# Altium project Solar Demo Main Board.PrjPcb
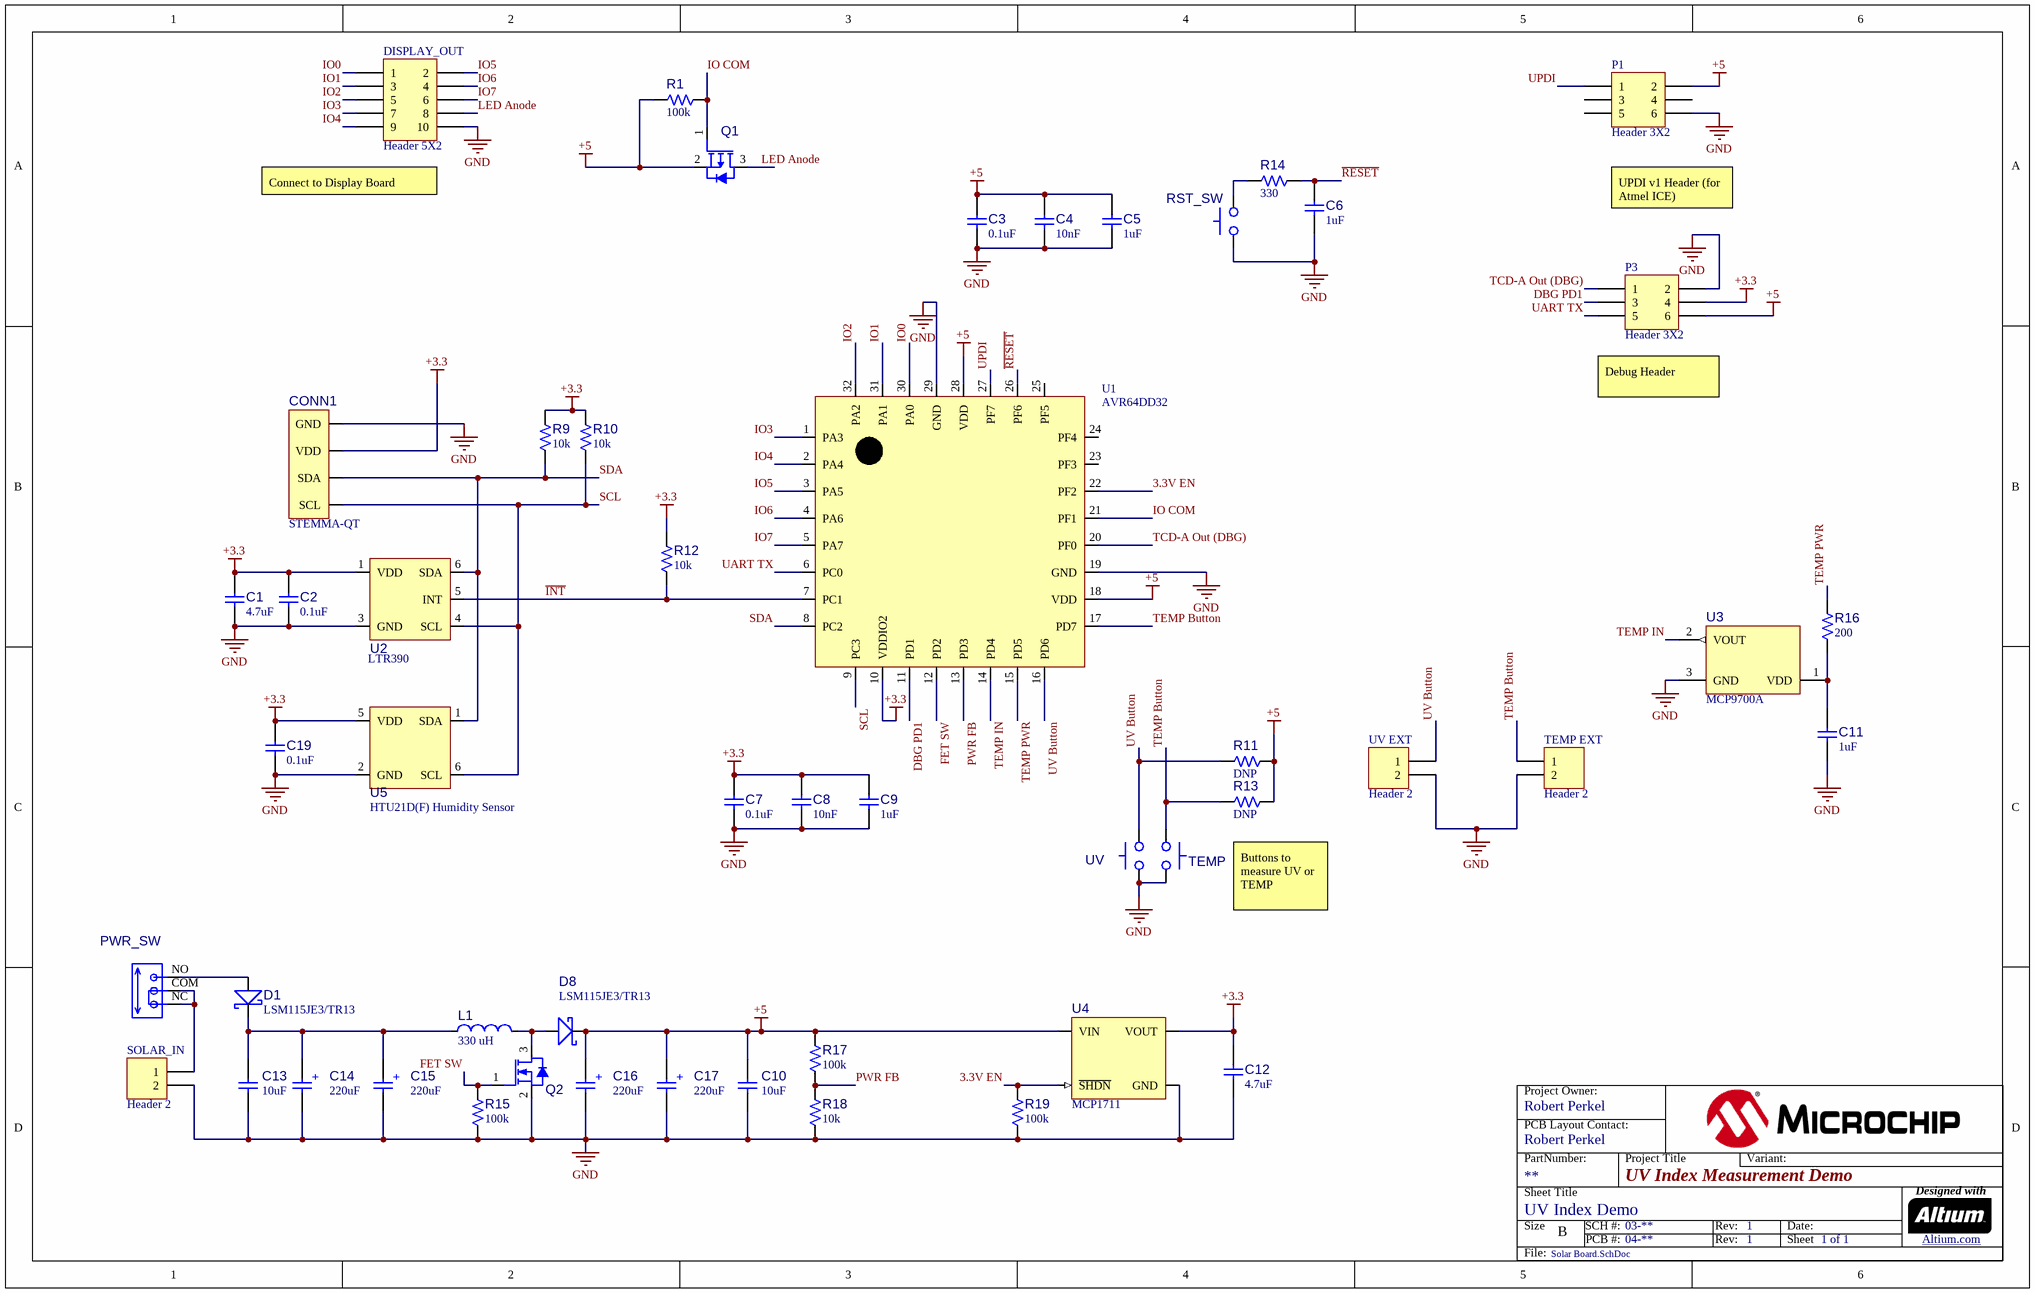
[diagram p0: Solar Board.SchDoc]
ProjectDrawnBy: Robert Perkel; ProjectEngineer: Robert Perkel; ProjectPartNumber: **; ProjectPCBAssyNumber: **; ProjectPCBNumber: **; ProjectRevisionART: 1; ProjectRevisionASSY: **; ProjectRevisionFAB: **; ProjectRevisionSCH: 1; ProjectTitle: UV Index Measurement Demo
1 sheet, 51 parts. Net scope: global (net labels, ports and power ports of the same name join across sheets).
Board file: Solar Board.PcbDoc

## Sheet Solar Board.SchDoc
size B; CompanyName: Microchip Technology Inc.; Organization: Microchip Technology; Address1: 2355 West Chandler Blvd.; Address2: Chandler, AZ  85224; Address4: USA; SheetNumber: 1; SheetTotal: 1; SheetTitle: UV Index Demo

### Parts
C1  value 4.7uF  [0805]  (hidden comment: Capacitor)
C2  value 0.1uF  [0805]  (hidden comment: Capacitor)
C3  value 0.1uF  [0805]  (hidden comment: Capacitor)
C4  value 10nF  [0805]  (hidden comment: Capacitor)
C5  value 1uF  [0805]  (hidden comment: Capacitor)
C6  value 1uF  [0805]  (hidden comment: Capacitor)
C7  value 0.1uF  [0805]  (hidden comment: Capacitor)
C8  value 10nF  [0805]  (hidden comment: Capacitor)
C9  value 1uF  [0805]  (hidden comment: Capacitor)
C10  value 10uF  [0805]  (hidden comment: Capacitor)
C11  value 1uF  [0805]  (hidden comment: Capacitor)
C12  value 4.7uF  [0805]  (hidden comment: Capacitor)
C13  value 10uF  [0805]  (hidden comment: Capacitor)
C14  value 220uF  [2917]  (hidden comment: Polarized Capacitor)
C15  value 220uF  [2917]  (hidden comment: Polarized Capacitor)
C16  value 220uF  [2917]  (hidden comment: Polarized Capacitor)
C17  value 220uF  [2917]  (hidden comment: Polarized Capacitor)
C19  value 0.1uF  [0805]  (hidden comment: Capacitor)
CONN1  STEMMA-QT  [JST-ST]
D1  Part Number: LSM115JE3/TR13  [DO-215AB]  (hidden comment: Schottky)
D8  Part Number: LSM115JE3/TR13  [DO-215AB]  (hidden comment: Schottky)
DISPLAY_OUT  Header 5X2  [HDR2X5]
L1  value 330 uH  [6mm x 6mm Inductor]  (hidden comment: Inductor)
P1  Header 3X2  [HDR2X3]
P3  Header 3X2  [HDR2X3]
PWR_SW  SPDT Slide  [CST11T2CR (SPST)]  (value not drawn)
Q1  PMOS Transistor  [SOT-23]  (value not drawn)
Q2  NMOS Transistor  [SOT-23]  (value not drawn)
R1  value 100k  [0805]  (hidden comment: Resistor)
R9  value 10k  [0805]  (hidden comment: Resistor)
R10  value 10k  [0805]  (hidden comment: Resistor)
R11  value DNP  [0805]  (hidden comment: Resistor)
R12  value 10k  [0805]  (hidden comment: Resistor)
R13  value DNP  [0805]  (hidden comment: Resistor)
R14  value 330  [0805]  (hidden comment: Resistor)
R15  value 100k  [0805]  (hidden comment: Resistor)
R16  value 200  [0805]  (hidden comment: Resistor)
R17  value 100k  [0805]  (hidden comment: Resistor)
R18  value 10k  [0805]  (hidden comment: Resistor)
R19  value 100k  [0805]  (hidden comment: Resistor)
RST_SW  SPST Switch  [KMR7]  (value not drawn)
SOLAR_IN  Header 2  [HDR1X2]
TEMP  SPST Switch  [KSC4]  (value not drawn)
TEMP_EXT  Header 2  [HDR1X2]
U1  AVR64DD32  [TQFP-32]
U2  LTR390  [Extended QFN-6]
U3  value MCP9700A  [SOT-23-3]  (hidden comment: MCP9700(A)_1(A) TO-92-3_SOT-23-3)
U4  MCP1711  [SOT23-5]
U5  HTU21D(F) Humidity Sensor  [HTU21D(F) Extended Package]
UV  SPST Switch  [KSC4]  (value not drawn)
UV_EXT  Header 2  [HDR1X2]

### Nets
+3.3: C1.1 C2.1 C7.1 C8.1 C9.1 C12.1 C19.1 CONN1.2(VDD) P3.4 R9.2 R10.2 R12.2 U1.10(VDDIO2) U2.1(VDD) U4.5(VOUT) U5.5(VDD)
+5: C3.1 C4.1 C5.1 C10.1 C16.A C17.A D8.K(CATHODE) P1.2 P3.6 Q1.2(S) R1.2 R11.1 R13.1 R17.2 U1.18(VDD) U1.28(VDD) U4.1(VIN)
GND: C1.2 C2.2 C3.2 C4.2 C5.2 C6.2 C7.2 C8.2 C9.2 C10.2 C11.2 C12.2 C13.2 C14.K C15.K C16.K C17.K C19.2 CONN1.1(GND) DISPLAY_OUT.10 P1.6 P3.2 Q2.2(S) R15.1 R18.1 R19.1 RST_SW.1 SOLAR_IN.2 TEMP.1 TEMP_EXT.2 U1.19(GND) U1.29(GND) U2.3(GND) U3.3(GND) U4.2(GND) U5.2(GND) UV.1 UV_EXT.2
3.3V EN: R19.2 U1.22(PF2) U4.3(~{SHDN})
DBG PD1: P3.3 U1.11(PD1)
FET SW: Q2.1(G) R15.2 U1.12(PD2)
~{INT}: R12.1 U1.7(PC1) U2.5(INT)
IO0: DISPLAY_OUT.1 U1.30(PA0)
IO1: DISPLAY_OUT.3 U1.31(PA1)
IO2: DISPLAY_OUT.5 U1.32(PA2)
IO3: DISPLAY_OUT.7 U1.1(PA3)
IO4: DISPLAY_OUT.9 U1.2(PA4)
IO5: DISPLAY_OUT.2 U1.3(PA5)
IO6: DISPLAY_OUT.4 U1.4(PA6)
IO7: DISPLAY_OUT.6 U1.5(PA7)
IO COM: Q1.1(G) R1.1 U1.21(PF1)
LED Anode: DISPLAY_OUT.8 Q1.3(D)
PWR FB: R17.1 R18.2 U1.13(PD3)
~{RESET}: C6.1 R14.1 U1.26(PF6)
SCL: CONN1.4(SCL) R10.1 U1.9(PC3) U2.4(SCL) U5.6(SCL)
SDA: CONN1.3(SDA) R9.1 U1.8(PC2) U2.6(SDA) U5.1(SDA)
TCD-A Out (DBG): P3.1 U1.20(PF0)
TEMP Button: R13.2 TEMP.2 TEMP_EXT.1 U1.17(PD7)
TEMP IN: U1.14(PD4) U3.2(VOUT)
TEMP PWR: R16.2 U1.15(PD5)
UART TX: P3.5 U1.6(PC0)
UPDI: P1.1 U1.27(PF7)
UV Button: R11.2 U1.16(PD6) UV.2 UV_EXT.1
NetC11_1: C11.1 R16.1 U3.1(VDD)
NetC13_1: C13.1 C14.A C15.A D1.K(CATHODE) L1.1
NetD1_A: D1.A(ANODE) PWR_SW.NO
NetD8_A: D8.A(ANODE) L1.2 Q2.3(D)
NetPWR_SW_COM: PWR_SW.COM PWR_SW.NC SOLAR_IN.1
NetR14_2: R14.2 RST_SW.2

Not connected (* = marked no-connect by the designer): P1 3 4 5; U1 23(PF3) 24(PF4) 25(PF5)

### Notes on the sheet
- (near DISPLAY_OUT) Connect to Display Board
- UPDI v1 Header (for Atmel ICE)
- (near P3) Debug Header
- (near R13) Buttons to measure UV or TEMP

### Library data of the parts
C14-C17 = Polarized Capacitor: Rated Voltage: 10V; Dielelectic: Tantalum
CONN1 = Stemma-QT: Used with JST-ST Cables; pin to pad: 1>1+MECH1+MECH2
DISPLAY_OUT = Header 5X2: Header, 5-Pin, Dual row; System: Connector
L1 = Inductor: Part Number: ASPI-6045S-331M-T
P1 P3 = Header 3X2: Header, 3-Pin, Dual row
PWR_SW = SPDT Slide: pin to pad: COM>5 NC>4 NO>6; Part Number: CST11T2CR
Q1 = PMOS: Part Number: SSM3J168F,LF
Q2 = NMOS: Part Number: DMN3731U-7
RST_SW = SPST: pin to pad: 1>1+4 2>2+3
SOLAR_IN TEMP_EXT UV_EXT = Header 2: Header, 2-Pin
TEMP UV = SPST: Part Number: KSC421G 70SH LFS
U3 = MIC3211: MCP97XX; Manufacturer 1: Microchip; Manufacturer Part Number 1: MCP9700AT-E/TT; Description_: MCHP ANALOG TEMPERATURE SENSOR -40C to +150C MCP9700AT-E/TT SOT-23-3; Dev Tools Status: Production; Populated: Yes
U5 = HTU21D: pin to pad: 2>2+PAD; Part Number: HPP845E131R5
